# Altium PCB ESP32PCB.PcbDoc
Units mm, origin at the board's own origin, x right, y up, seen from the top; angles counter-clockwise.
Board outline 110 x 90 mm, 2 copper layers (Top Layer, Bottom Layer); 120 components, 72 nets, 375 pads, 60 vias.
Unrouted connection lines stored in the file: 1.
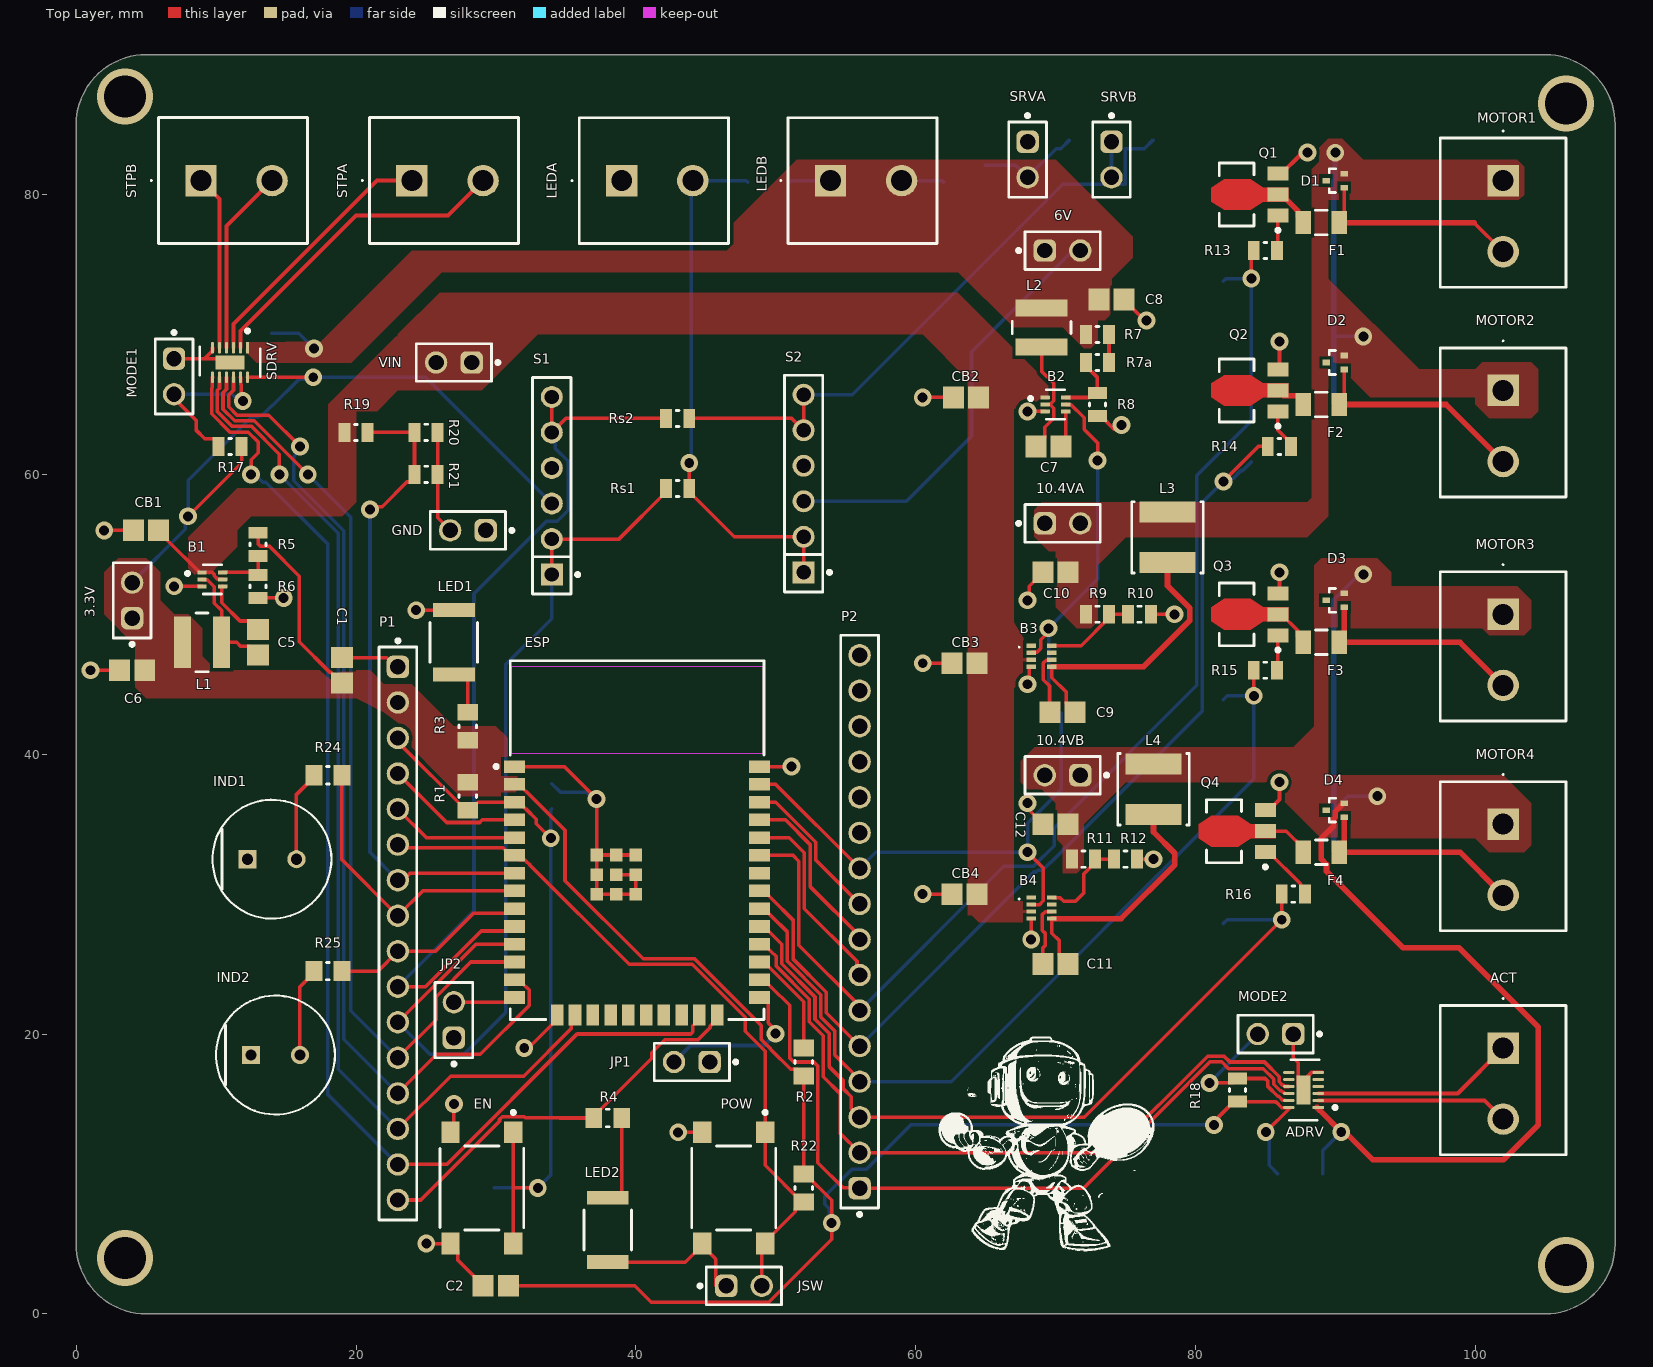
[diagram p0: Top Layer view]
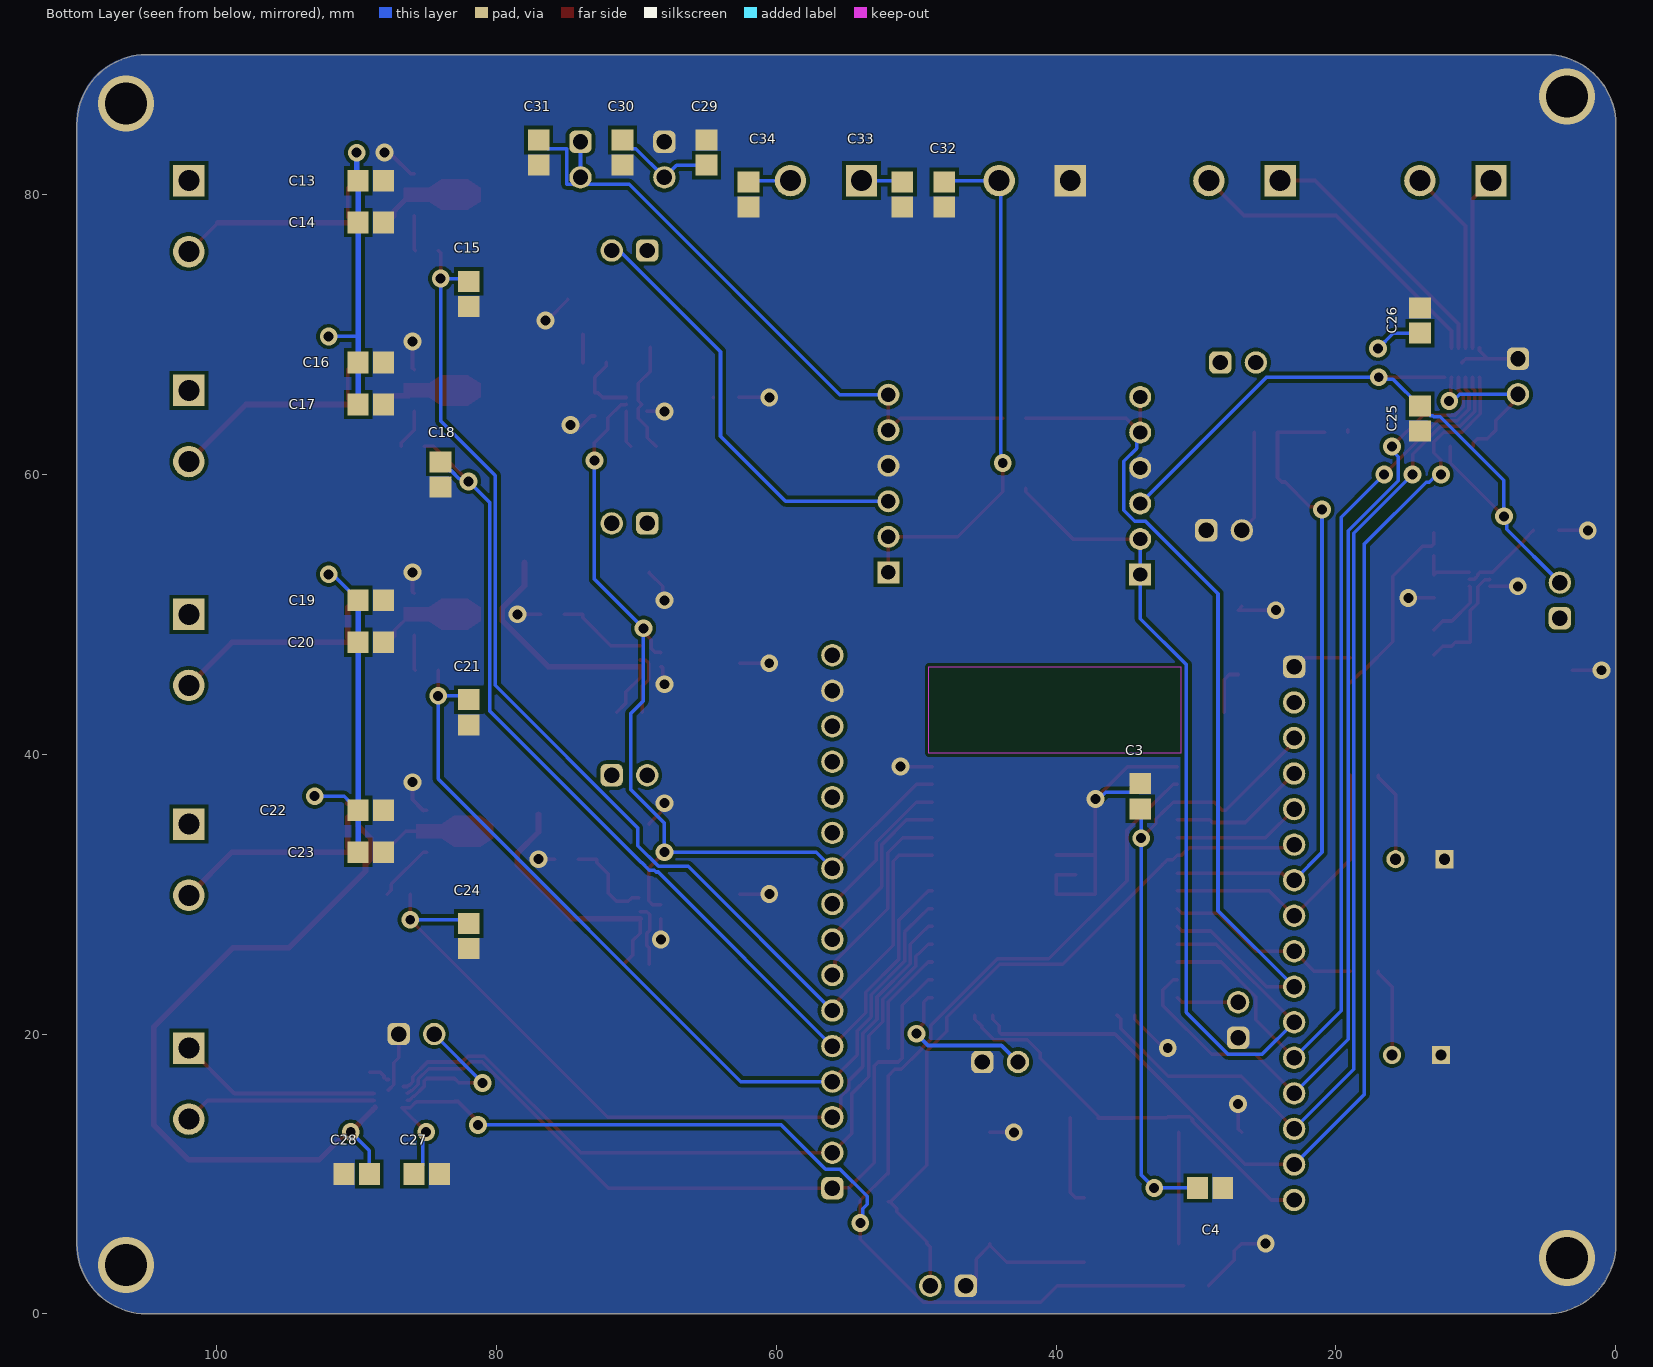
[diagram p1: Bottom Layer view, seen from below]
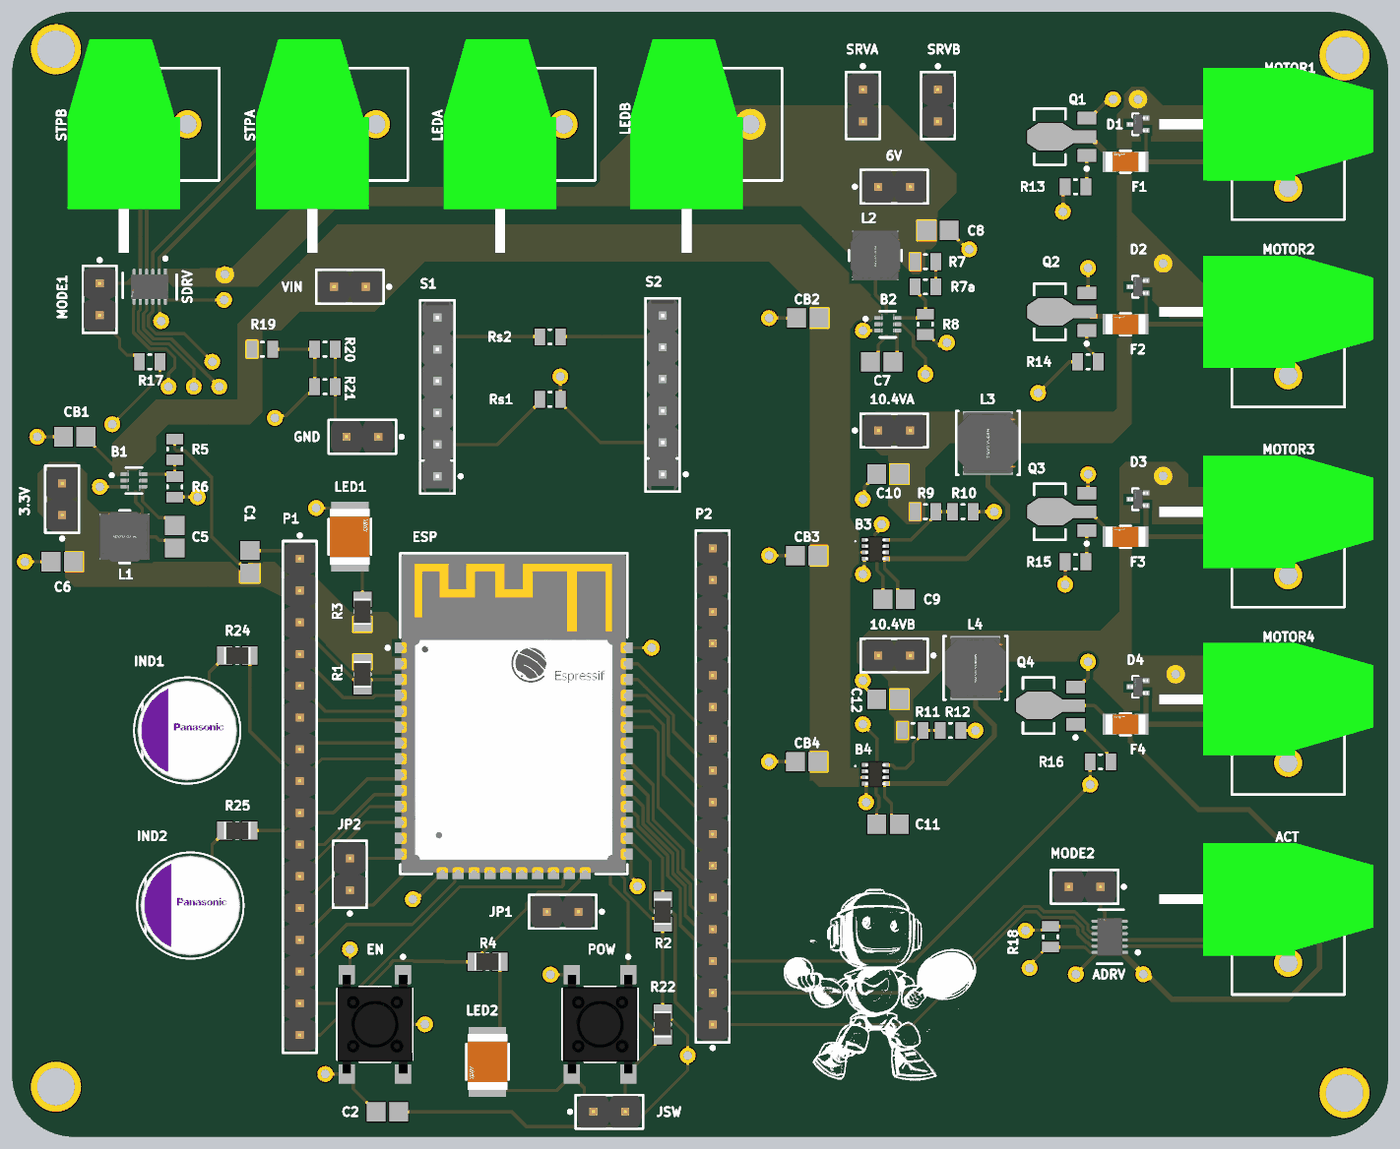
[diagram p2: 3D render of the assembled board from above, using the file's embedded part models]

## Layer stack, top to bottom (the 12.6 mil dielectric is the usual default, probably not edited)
Top Solder: solder mask 0.0102, Solder Resist, Dk 3.5
Top Layer: signal copper 0.0356
Dielectric 1: dielectric 0.32, FR-4, Dk 4.8
Bottom Layer: signal copper 0.0356
Bottom Solder: solder mask 0.0102, Solder Resist, Dk 3.5

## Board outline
0,5 ccw(c5,5) 5,0 105,0 ccw(c105,5) 110,5 110,85 ccw(c105,85) 105,90 5,90 ccw(c5,85) 0,85

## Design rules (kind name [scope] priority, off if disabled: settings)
Clearance Clearance_1 [IsPad] p1: gap=0.254 ignorepadtopadclearanceinfootprint=TRUE except(0.15: Arc-SMDPad Track-SMDPad SMDPad-SMDPad; 0.2: Arc-Arc Arc-Track Track-Track)
Clearance Clearance_1 [OnMid vs OnMid] p2: gap=0.254 ignorepadtopadclearanceinfootprint=FALSE except(0.15: Arc-Arc Arc-Track Arc-SMDPad Arc-Text Track-Track Track-SMDPad Track-Text SMDPad-SMDPad SMDPad-Text Text-Text) sourcerule=40 cellrowname=All cellrowtype=0 cellcolname=All cellcoltype=0 innerlayers=TRUE
Clearance Clearance_2 [(ExistsOnLayer('Top Layer') Or ExistsOnLayer('Bottom Layer')) vs (ExistsOnLayer('Top Layer') Or ExistsOnLayer('Bottom Layer'))] p3: gap=0.254 ignorepadtopadclearanceinfootprint=FALSE except(0.15: Arc-Arc Arc-Track Arc-SMDPad Arc-Text Track-Track Track-SMDPad Track-Text SMDPad-SMDPad SMDPad-Text Text-Text) sourcerule=40 cellrowname=All cellrowtype=0 cellcolname=All cellcoltype=0 outerlayers=TRUE
Clearance [All] p4: gap=0.254 ignorepadtopadclearanceinfootprint=FALSE ismatrix=TRUE
HoleSize [All] p1: absolutevalues=TRUE maxlimit=5 minlimit=0.025 maxpercent=80.000 minpercent=20.000
MinimumSolderMaskSliver [All] p1: minsoldermaskwidth=0.08
NetAntennae [All] p1 off: netantennaetolerance=0
PlaneClearance PlaneClearance_1 [(InNet('14.4V') OR InNet('10.4VA'))] p1: clearance=0
PlaneClearance [All] p2: clearance=0.508
PlaneConnect [All] p1: planeconnectstyle=Direct reliefexpansion=0.508 reliefentries=4 reliefconductorwidth=0.254 reliefairgap=0.254
PolygonConnect [All] p1: connectstyle=Direct reliefconductorwidth=0.254 reliefentries=4 polygonreliefangle="90 Angle" airgapwidth=0.254
RoutingVias [All] p1: holewidth=0.711 width=1.27 viastyle="Through Hole" minholewidth=0.711 minwidth=1.27 maxholewidth=0.711 maxwidth=1.27
SilkToSolderMaskClearance SilkToSolderMaskClearance_1 [(InNet('3.3V') AND InComponent('3.3V'))] p1: minsilkscreentomaskgap=0.254 clearancetoexposedcopper=TRUE
SilkToSolderMaskClearance [IsPad] p2: minsilkscreentomaskgap=0.16 clearancetoexposedcopper=TRUE
SolderMaskExpansion [All] p1: expansion=0.102 istentingtop=FALSE
SupplyNets "Schematic Supply Nets_1" [InNet('GND')] p1: voltage=0.000
Width [All] p1: maxlimit=0.5 minlimit=0.254 preferedwidth=0.254 minimp=50.000000 maximp=50.000000 favimp=50.000000
24 further rules are at their usual default settings.

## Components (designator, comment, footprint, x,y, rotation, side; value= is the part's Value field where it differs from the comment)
3.3V "3V3" 61300211121 3.994,50.997 r90 top
6V "6V" 61300211121 70.5,76 r0 top
10.4VA "10V4" 61300211121 70.5,56.5 r0 top
10.4VB "10V4" 61300211121 70.5,38.5 r180 top
ACT "EBAFA-02-D" EBAFA02D 101.994,18.997 r270 top
ADRV "DRV8835DSSR" FP-DSS0012A-IPC_A 87.724,15.997 r180 top
B1 "TPS562231DRLR" FP-DRL0006A-MFG 9.734,52.497 r0 top
B2 "TPS562231DRLR" FP-DRL0006A-MFG 69.994,64.997 r0 top
B3 "TPS563300DRLR" TPS62932DRLR 69,47 r0 top
B4 "TPS563300DRLR" TPS62932DRLR 69,29 r0 top
C1 "22uF" CAPC2013X145X50ML20T25 18.994,45.997 r270 top
C2 "0.1uF" CAPC2013X145X50ML20T25 29.994,1.997 r0 top
C3 "0.1uF" CAPC2013X145X50ML20T25 33.994,36.997 r270 bottom
C4 "0.1uF" CAPC2013X145X50ML20T25 28.994,8.997 r180 bottom
C5 "0.1uF" CAPC2013X145X50ML20T25 12.994,47.997 r90 top
C6 "47uF" CAPC2013X145X50ML20T25 4,46 r180 top
C7 "0.1uF" CAPC2013X145X50ML20T25 69.5,62 r0 top
C8 "47uF" CAPC2013X145X50ML20T25 74,72.5 r0 top
C9 "0.1uF" CAPC2013X145X50ML20T25 70.5,43 r180 top
C10 "47uF" CAPC2013X145X50ML20T25 70,53 r180 top
C11 "0.1uF" CAPC2013X145X50ML20T25 70,25 r180 top
C12 "47uF" CAPC2013X145X50ML20T25 70,35 r180 top
C13 "22uF" CAPC2013X145X50ML20T25 88.994,80.997 r180 bottom
C14 "0.1uF" CAPC2013X145X50ML20T25 88.994,77.997 r180 bottom
C15 "0.1uF" CAPC2013X145X50ML20T25 81.994,72.897 r270 bottom
C16 "22uF" CAPC2013X145X50ML20T25 88.994,67.997 r180 bottom
C17 "0.1uF" CAPC2013X145X50ML20T25 88.994,64.997 r180 bottom
C18 "0.1uF" CAPC2013X145X50ML20T25 84,60 r270 bottom
C19 "22uF" CAPC2013X145X50ML20T25 88.994,50.997 r180 bottom
C20 "0.1uF" CAPC2013X145X50ML20T25 88.994,47.997 r180 bottom
C21 "0.1uF" CAPC2013X145X50ML20T25 81.994,42.997 r270 bottom
C22 "22uF" CAPC2013X145X50ML20T25 88.994,35.997 r180 bottom
C23 "0.1uF" CAPC2013X145X50ML20T25 88.994,32.997 r180 bottom
C24 "0.1uF" CAPC2013X145X50ML20T25 81.994,26.997 r270 bottom
C25 "0.1uF" CAPC2013X145X50ML20T25 13.994,63.997 r270 bottom
C26 "0.1uF" CAPC2013X145X50ML20T25 13.994,70.997 r90 bottom
C27 "0.1uF" CAPC2013X145X50ML20T25 84.994,9.997 r180 bottom
C28 "0.1uF" CAPC2013X145X50ML20T25 89.994,9.997 r0 bottom
C29 "22uF" CAPC2013X145X50ML20T25 64.994,82.997 r90 bottom
C30 "0.1uF" CAPC2013X145X50ML20T25 70.994,82.997 r270 bottom
C31 "0.1uF" CAPC2013X145X50ML20T25 76.994,82.997 r270 bottom
C32 "0.1uF" CAPC2013X145X50ML20T25 47.994,79.997 r270 bottom
C33 "22uF" CAPC2013X145X50ML20T25 50.994,79.997 r270 bottom
C34 "0.1uF" CAPC2013X145X50ML20T25 61.994,79.997 r270 bottom
CB1 "10uF" CAPC2013X145X50ML20T25 4.994,55.997 r180 top
CB2 "10uF" CAPC2013X145X50ML20T25 63.6,65.5 r180 top
CB3 "10uF" CAPC2013X145X50ML20T25 63.5,46.5 r180 top
CB4 "10uF" CAPC2013X145X50ML20T25 63.5,30 r180 top
D1 "BAV99T-7-F" FP-SOT523-MFG 89.994,80.997 r180 top value=1.5pF
D2 "BAV99T-7-F" FP-SOT523-MFG 89.994,67.997 r180 top value=1.5pF
D3 "BAV99T-7-F" FP-SOT523-MFG 89.994,50.997 r180 top value=1.5pF
D4 "BAV99T-7-F" FP-SOT523-MFG 89.994,35.997 r180 top value=1.5pF
EN "EN" FP-PTS645SM43SMTR92LFS-MFG 28.994,8.997 r270 top
ESP "ESP32-WROOM-32E (4MB)" FP-ESP32-WROOM-32E_4MB-MFG 40.094,33.857 r0 top
F1 "" FP-GRM319-0_15-IPC_C 88.994,77.997 r180 top
F2 "" FP-GRM319-0_15-IPC_C 88.994,64.997 r180 top
F3 "" FP-GRM319-0_15-IPC_C 88.994,47.997 r180 top
F4 "" FP-GRM319-0_15-IPC_C 88.994,32.997 r180 top
GND "GND" 61300211121 27.994,55.997 r180 top
IND1 "" FP-OS-CON-TH-E12-d_0_6-MFG 13.994,32.497 r0 top
IND2 "" FP-OS-CON-TH-E12-d_0_6-MFG 14.244,18.497 r0 top
JP1 "BOOT" 61300211121 44,18 r180 top
JP2 "IO12" 61300211121 26.994,20.997 r90 top
JSW "" 61300211121 47.73,2 r0 top
L1 "3.3uH" FP-NR4012-MFG 8.994,47.997 r180 top
L2 "3.3uH" FP-NR4012-MFG 69,70.5 r90 top
L3 "6.8uH" FP-NRS5030-H_3_1-MFG 78,55.5 r90 top
L4 "6.8uH" FP-NRS5030-H_3_1-MFG 77,37.5 r90 top
LED1 "GREEN" FP-1812-L_4_5_0_3-W_3_2_0-MFG 26.994,47.997 r90 top
LED2 "YELLOW" FP-1812-L_4_5_0_3-W_3_2_0-MFG 37.994,5.997 r270 top
LEDA "EBAFA-02-D" EBAFA02D 38.994,80.997 r0 top
LEDB "EBAFA-02-D" EBAFA02D 53.914,80.997 r0 top
MODE1 "" 61300211121 6.994,66.997 r270 top
MODE2 "" 61300211121 85.724,19.997 r180 top
MOTOR1 "EBAFA-02-D" EBAFA02D 101.994,80.997 r270 top
MOTOR2 "EBAFA-02-D" EBAFA02D 101.994,65.997 r270 top
MOTOR3 "EBAFA-02-D" EBAFA02D 101.994,49.997 r270 top
MOTOR4 "EBAFA-02-D" EBAFA02D 101.994,34.997 r270 top
P1 "L_CONN" 61301611121 22.994,27.187 r270 top
P2 "R_CONN" 61301611121 55.994,28.027 r90 top
POW "" FP-PTS645SM43SMTR92LFS-MFG 46.994,8.997 r270 top
Q1 "2SC5566-TD-E" ONSC-SOT-89_PCP-1-3-419AU_V 82.994,79.997 r90 top
Q2 "2SC5566-TD-E" ONSC-SOT-89_PCP-1-3-419AU_V 82.994,65.997 r90 top
Q3 "2SC5566-TD-E" ONSC-SOT-89_PCP-1-3-419AU_V 82.994,49.997 r90 top
Q4 "2SC5566-TD-E" ONSC-SOT-89_PCP-1-3-419AU_V 82.094,34.497 r90 top
R1 "10k" RESC2013X60X35ML10T20 27.994,36.997 r270 top
R2 "10k" RESC2013X60X35ML10T20 52,18 r90 top
R3 "100" RESC2013X60X35ML10T20 27.994,41.997 r90 top
R4 "100" RESC2013X60X35ML10T20 37.994,13.997 r0 top
R5 "45.3k" RESC2013X50X30LL20T20 13,55 r270 top
R6 "10k" RESC2013X50X30LL20T20 12.994,51.997 r270 top
R7 "45.3k" RESC2013X50X30LL20T20 73,70 r0 top
R7a "45.3k" RESC2013X50X30LL20T20 72.994,67.997 r0 top
R8 "10k" RESC2013X50X30LL20T20 72.994,64.997 r270 top
R9 "120k" RESC2013X50X30LL20T20 73,50 r0 top
R10 "10k" RESC2013X50X30LL20T20 76,50 r0 top
R11 "120k" RESC2013X50X30LL20T20 72,32.5 r0 top
R12 "10k" RESC2013X50X30LL20T20 75,32.5 r0 top
R13 "1k" RESC2013X50X30LL20T20 84.994,75.997 r0 top
R14 "1k" RESC2013X50X30LL20T20 85.994,61.997 r0 top
R15 "1k" RESC2013X50X30LL20T20 84.994,45.997 r0 top
R16 "1k" RESC2013X50X30LL20T20 86.994,29.997 r0 top
R17 "10k" RESC2013X50X30LL20T20 11,62 r0 top
R18 "10k" RESC2013X50X30LL20T20 83,16 r270 top
R19 "10k" RESC2013X50X30LL20T20 19.994,62.997 r0 top
R20 "100k" RESC2013X50X30LL20T20 25.006,63.003 r0 top
R21 "100k" RESC2013X50X30LL20T20 25.006,60.003 r0 top
R22 "10k" RESC2013X60X35ML10T20 51.994,8.997 r270 top
R24 "100" RESC2013X60X35ML10T20 17.994,38.497 r180 top
R25 "100" RESC2013X60X35ML10T20 17.994,24.497 r180 top
Rs1 "0" RESC2013X50X30LL20T20 42.994,58.997 r0 top
Rs2 "0" RESC2013X50X30LL20T20 42.994,63.997 r0 top
S1 "" FP-22-28-4060-MFG 33.994,59.187 r90 top
S2 "" FP-22-28-4060-MFG 51.994,59.347 r90 top
SDRV "DRV8835DSSR" FP-DSS0012A-IPC_A 10.994,67.997 r270 top
SRVA "" 61300211121 68,82.5 r270 top
SRVB "" 61300211121 74,82.5 r270 top
STPA "EBAFA-02-D" EBAFA02D 24,81 r0 top
STPB "EBAFA-02-D" EBAFA02D 8.92,81 r0 top
VIN "14.4V" 61300211121 26.994,67.997 r180 top

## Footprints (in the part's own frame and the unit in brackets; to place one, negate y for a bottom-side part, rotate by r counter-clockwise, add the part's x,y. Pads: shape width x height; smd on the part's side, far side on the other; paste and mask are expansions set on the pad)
61300211121 [mm] "Pin Header, pitch 2.54 mm, THT, Vertical, single row, 2p"
  rrect50% 1.6x1.6 hole 1.1: 1(-1.27,0)
  round 1.6 hole 1.1: 2(1.27,0)
  silkscreen extent -3.26,-1.35 2.69,1.35, body extent -2.54,-1.27 2.54,1.27, height 8.57
61301611121 [mm] "Pin Header, pitch 2.54 mm, THT, Vertical, single row, 16p"
  rrect50% 1.6x1.6 hole 1.1: 1(-19.05,0)
  round 1.6 hole 1.1: 2(-16.51,0) 3(-13.97,0) 4(-11.43,0) 5(-8.89,0) 6(-6.35,0) 7(-3.81,0) 8(-1.27,0) 9(1.27,0) 10(3.81,0) 11(6.35,0) 12(8.89,0) 13(11.43,0) 14(13.97,0) 15(16.51,0) 16(19.05,0)
  silkscreen extent -21.04,-1.35 20.47,1.35, body extent -20.32,-1.27 20.32,1.27, height 8.57
CAPC2013X145X50ML20T25 [mm] "Chip Capacitor, 2-Leads, Body 2.00x1.25mm, IPC Low Density"
  rect 1.5x1.55 smd: 1(-0.9,0) 2(0.9,0)
  body extent -1.1,-0.72 1.1,0.72, height 1.45
EBAFA02D [mm]
  rect 2.25x2.25 hole 1.5: 1(0,0)
  round 2.25 hole 1.5: 2(5.08,0)
  silkscreen extent -3.6,-4.5 7.62,4.5, body extent -4.5,-10.3 4.5,6.8, height 5.08
FP-22-28-4060-MFG [mm]
  rect 1.57x1.57 hole 1.02 paste-2539.97 mask+0: 1(-6.35,0)
  round 1.57 hole 1.02 paste-2539.97 mask+0: 2(-3.81,0) 3(-1.27,0) 4(1.27,0) 5(3.81,0) 6(6.35,0)
  silkscreen extent -7.75,-1.97 7.75,1.37, body extent -7.85,-1.47 7.85,1.47, height 0.25
FP-1812-L_4_5_0_3-W_3_2_0-MFG [mm]
  rect 1x3 smd paste+0 mask+0: 1(-2.3,0) 2(2.3,0)
  silkscreen extent -1.43,-1.7 1.43,1.7, body extent -2.9,-1.8 2.9,1.8, height 0.25
FP-DRL0006A-MFG [mm]
  rrect33% 0.67x0.3 smd paste+0 mask+0: 1(-0.74,0.5) 2(-0.74,0) 3(-0.74,-0.5) 4(0.74,-0.5) 5(0.74,0) 6(0.74,0.5)
  silkscreen extent -1.9,-1.05 0.65,1.05, body extent -1.17,-1.1 1.17,1.1, height 0.25
FP-DSS0012A-IPC_A [mm]
  rect 0.806x0.242 smd paste+0 mask+0: 1(-1.053,1.25)
  rrect100% 0.806x0.242 smd paste+0 mask+0: 2(-1.053,0.75) 3(-1.053,0.25) 4(-1.053,-0.25) 5(-1.053,-0.75) 6(-1.053,-1.25) 7(1.053,-1.25) 8(1.053,-0.75) 9(1.053,-0.25) 10(1.053,0.25) 11(1.053,0.75) 12(1.053,1.25)
  rect 1x2.1 smd paste-1000 mask+0: 13(0,0)
  silkscreen extent -2.38,-2.16 1.02,2.16, body extent -1.96,-2 1.96,2, height 0.25
FP-ESP32-WROOM-32E_4MB-MFG [mm]
  rect 1.5x0.9 smd paste+0 mask+0: 1(-8.75,5.26) 2(-8.75,3.99) 3(-8.75,2.72) 4(-8.75,1.45) 5(-8.75,0.18) 6(-8.75,-1.09) 7(-8.75,-2.36) 8(-8.75,-3.63) 9(-8.75,-4.9) 10(-8.75,-6.17) 11(-8.75,-7.44) 12(-8.75,-8.71) 13(-8.75,-9.98) 14(-8.75,-11.25) 25(8.75,-11.25) 26(8.75,-9.98) 27(8.75,-8.71) 28(8.75,-7.44) 29(8.75,-6.17) 30(8.75,-4.9) 31(8.75,-3.63) 32(8.75,-2.36) 33(8.75,-1.09) 34(8.75,0.18) 35(8.75,1.45) 36(8.75,2.72) 37(8.75,3.99) 38(8.75,5.26)
  rect 0.9x1.5 smd paste+0 mask+0: 15(-5.71,-12.5) 16(-4.44,-12.5) 17(-3.17,-12.5) 18(-1.9,-12.5) 19(-0.63,-12.5) 20(0.64,-12.5) 21(1.91,-12.5) 22(3.18,-12.5) 23(4.45,-12.5) 24(5.72,-12.5)
  rect 0.9x0.9 smd paste+0 mask+0: 39(-2.9,-3.86) 39(-2.9,-2.46) 39(-2.9,-1.06) 39(-1.5,-3.86) 39(-1.5,-2.46) 39(-1.5,-1.06) 39(-0.1,-3.86) 39(-0.1,-2.46) 39(-0.1,-1.06)
  Keep-Out Layer region: -9,6.205 9,6.205 9,12.395 -9,12.395
  Keep-Out Layer region: -9,6.205 9,6.205 9,12.395 -9,12.395
  silkscreen extent -10.2,-12.83 9.08,12.83, body extent -9.6,-13.35 9.6,12.93, height 0.25
FP-GRM319-0_15-IPC_C [mm]
  rect 1.106x1.658 smd paste+0 mask+0: 1(-1.276,0) 2(1.276,0)
  silkscreen extent -0.42,-0.87 0.42,0.87, body extent -1.93,-0.97 1.93,0.97, height 0.25
FP-NR4012-MFG [mm]
  rect 1.2x3.7 smd paste+0 mask+0: 1(-1.4,0) 2(1.4,0)
  silkscreen extent -0.43,-2.1 0.43,2.1, body extent -2.2,-2.2 2.2,2.2, height 0.25
FP-NRS5030-H_3_1-MFG [mm]
  rect 1.5x4 smd paste+0 mask+0: 1(-1.8,0) 2(1.8,0)
  silkscreen extent -2.55,-2.55 2.55,2.55, body extent -2.65,-2.65 2.65,2.65, height 0.25
FP-OS-CON-TH-E12-d_0_6-MFG [mm]
  rect 1.3x1.3 hole 0.8 paste-2539.97 mask+0: 1(-1.75,0)
  round 1.3 hole 0.8 paste-2539.97 mask+0: 2(1.75,0)
  silkscreen extent -4.25,-4.25 4.25,4.25, body extent -4.35,-4.35 4.35,4.35, height 0.25
FP-PTS645SM43SMTR92LFS-MFG [mm]
  rect 1.55x1.3 smd paste+0 mask+0: 1(-3.975,2.25) 2(3.975,2.25) 3(-3.975,-2.25) 4(3.975,-2.25)
  silkscreen extent -5.52,-3 3,3, body extent -4.85,-3.1 4.85,3.1, height 0.25
FP-SOT523-MFG [mm]
  rect 0.51x0.4 smd paste+0 mask+0: 1(-0.645,0.5) 2(-0.645,-0.5) 3(0.645,0)
  silkscreen extent -0.02,-0.85 0.43,0.85, body extent -1,-0.95 1,0.95, height 0.25
ONSC-SOT-89_PCP-1-3-419AU_V [mm] "SOT89, 3-Leads, Body 4.5x2.5mm, Pitch 1.5mm"
  rect 1x1.5 smd: 1(-1.5,-2.9) 2(0,-2.9) 3(1.5,-2.9)
  Top Layer region: -0.5,-3.65 -0.5,-1.85 -1.1,-0.95 -1.1,0.95 -0.5,1.85 0.5,1.85 1.1,0.95 1.1,-0.95 0.5,-1.85 0.5,-3.65
  silkscreen extent -2.67,-3.03 2.25,1.3, body extent -2.25,-1.2 2.25,1.3, height 1.6
RESC2013X50X30LL20T20 [mm] "Chip Resistor, 2-Leads, Body 2.00x1.25mm, IPC High Density"
  rect 0.85x1.35 smd: 1(-0.825,0) 2(0.825,0)
  silkscreen extent -0.1,-0.58 0.1,0.58, body extent -1.1,-0.72 1.1,0.72, height 0.5
RESC2013X60X35ML10T20 [mm] "Chip Resistor, 2-Leads, Body 2.1x1.35mm, IPC Low Density"
  rect 1.2x1.45 smd: 1(-1,0) 2(1,0)
  silkscreen extent -0.1,-0.63 0.1,0.63, body extent -1.05,-0.68 1.05,0.67, height 0.6
TPS62932DRLR [mm]
  rect 0.67x0.3 smd: 1(-0.74,0.75) 2(-0.74,0.25) 3(-0.74,-0.25) 4(-0.74,-0.75) 5(0.74,-0.75) 6(0.74,-0.25) 7(0.74,0.25) 8(0.74,0.75)
  silkscreen extent -1.65,0.6 -1.55,0.7, body extent -0.8,-1.05 0.8,1.05, height 0.6

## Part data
3.3V 6V 10.4VA 10.4VB GND JP1 JP2 JSW MODE1 MODE2 SRVA SRVB VIN: library part CMP-1712-00002-6, Color=Black, Contact Resistance=20mΩ, Current Rating=3A, Max Operating Temperature=125°C, Min Operating Temperature=-40°C, Operating Supply Voltage=250V
ACT LEDA LEDB MOTOR1 MOTOR2 MOTOR3 MOTOR4 STPA STPB: "Connector", Manufacturer_Name="Adam Tech"
ADRV SDRV: library part CMP-00024-00007-1, "Brush DC Motor Controller, 1.5A, PDSO12", Case/Package=HVSON, Max Operating Temperature=85°C, Min Operating Temperature=-40°C, Nominal Supply Voltage=3V
B1 B2: library part CMP-04918-000372-1, "POWER MANAGEMENT"
B3 B4: "Integrated Circuit", Manufacturer_Name="Texas Instruments", Mouser Part Number=595-TPS563300DRLR
C1 C2 C3 C4 C5 C6 C7 C8 C9 C10 C11 C12 C13 C14 C15 C16 C17 C18 C19 C20 C21 C22 C23 C24 C25 C26 C27 C28 C29 C30 C31 C32 C33 C34 CB1 CB2 CB3 CB4: library part CMP-1036-04819-2, Manufacturer=Kemet, Part Number=C0805C225K9PACTU
D1 D2 D3 D4: library part CMP-12791-000024-1, "DIODE ARRAY GP 85V 75MA SOT523", Capacitance=1.5pF, Forward Current=75mA, Manufacturer="Diodes Inc.", Max Junction Temp=+150°C, Max Repetitive Reverse Voltage=85V, Max Surge Forward Current=0.5A, Package=SOT523, Peak Reverse Current=2uA, Temperature="-65°C to +150°C", Temperature Range Low=-65°C
EN POW: library part CMP-2000-05160-2, "SWITCH TACTILE SPST-NO 0.05A 12V", Case/Package=SMD/SMT, Color=Black, Contact Resistance=100mR, Current Rating=50mA, Max Operating Temperature=60°C, Max Voltage Rating (DC)=12V, Min Operating Temperature=-20°C, Operating Force=160gf, Package Quantity=1
ESP: library part CMP-194065-000026-1, "RX TXRX MOD WIFI TRACE ANT SMD"
F1 F2 F3 F4: library part CMP-1037-03764-2, "Chip Multilayer Ceramic Capacitors for General Purpose, 1206, 22000pF, C0G, 30ppm/°C, 5%, 50V", Capacitance=22nF, Case Code (Imperial)=1206, Case Code (Metric)=3216, Dielectric=C0G, Dielectric Material=Ceramic, Insulation Resistance=10GR, Max Operating Temperature=125°C, Min Operating Temperature=-55°C, Package Quantity=4000, Temperature Coefficient=30ppm/°C, Tolerance=5%, Voltage=50V
IND1 IND2: library part CMP-05428-001155-1, "Conductive Polymer Aluminum Solid Capacitors (OS-CON) 270uF ±20% 16V RADIAL TH 8x12mm", Capacitance=270uF, Case/Package=Radial, ESR (Equivalent Series Resistance)=11mR, Leakage Current=864uA, Max Operating Temperature=105°C, Min Operating Temperature=-55°C, Package Quantity=1000, Ripple Current=5A, Tolerance=20%, Voltage=16V
L1 L2: library part CMP-14484-001001-1, "SMD Power Inductors 3.3uH ±20% 1.4A 84mΩ", Case/Package=4012, Current Rating=1.7A, DC Resistance (DCR)=84mR, Inductance Tolerance=20%, Max Operating Temperature=125°C, Min Operating Temperature=-25°C, Package Quantity=1, Resistor Type=Wirewound, Saturation Current=1.4A, Self Resonant Frequency=60MHz, Test Frequency=100kHz
L3 L4: library part CMP-14484-000674-1, "Inductor Power Shielded Wirewound 6.8uH 20% 100KHz Ferrite 2.3A 67.6mΩ DCR T/R", Case/Package=5030, Current Rating=2.3A, DC Resistance (DCR)=52mR, Max DC Current=2.5A, Max Operating Temperature=120°C, Min Operating Temperature=-25°C, Package Quantity=500, Self Resonant Frequency=22MHz, Test Frequency=100kHz, Tolerance=20%
LED1 LED2: library part CMP-1040-01548-3, "General Purpose Ceramic Capacitor, 1812, 470nF, 10%, X7R, 15%, 100V", Capacitance=470nF, Case Code (Imperial)=1812, Case Code (Metric)=4532, Dielectric=X7R, Max Operating Temperature=125°C, Min Operating Temperature=-55°C, Package Quantity=1, Tolerance=10%, Voltage=100V
P1 P2: library part CMP-1502-01095-4, Color=Black, Contact Resistance=20mΩ, Current Rating=3A, Max Operating Temperature=105°C, Min Operating Temperature=-40°C, Operating Supply Voltage=250V
Q1 Q2 Q3 Q4: library part CMP-1048-00945-1, "Bipolar Transistor, 50 V, 4 A, Low VCE(sat), NPN Single, 3-Pin SOT-89, Pb-Free, Tape and Reel", Manufacturer="On Semiconductor"
R1 R2 R3 R4 R22 R24 R25: library part CMP-2100-03671-1, "Chip Resistor, 1 KOhm, +/- 1%, 125 mW, -55 to 155 degC, 0805 (2012 Metric), RoHS, Tape and Reel", Case Code (Imperial)=0805, Case Code (Metric)=2012, Manufacturer=Yageo, Max Operating Temperature=155degC, Max Power Dissipation=125mW, Min Operating Temperature=-55degC, Package Description="2-Pin Surface Mounted Device, Body 2 x 1.25 mm", Package Quantity=1, Resistance=1KOhm, Temperature Coefficient=100ppm/degreesC, Tolerance=1%, Voltage Rating=150V
R5 R6 R7 R7a R8 R9 R10 R11 R12 R13 R14 R15 R16 R17 R18 R19 R20 R21 Rs1 Rs2: library part CMP-2001-04896-1, Manufacturer="Vishay Dale", Part Number=CRCW08050000Z0EA
S1 S2: library part CMP-04776-000763-1, "CONN HEADER VERT 6POS 2.54MM", Color=Black, Contact Resistance=20mR, Current Rating=4A, Max Operating Temperature=75°C, Max Voltage Rating (AC)=250V, Max Voltage Rating (DC)=250.25kV, Min Operating Temperature=0°C, Package Quantity=1

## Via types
v1: diameter 1.27, hole 0.711, Top Layer to Bottom Layer, 56 vias
v2: diameter 4, hole 3, Top Layer to Bottom Layer, 4 vias

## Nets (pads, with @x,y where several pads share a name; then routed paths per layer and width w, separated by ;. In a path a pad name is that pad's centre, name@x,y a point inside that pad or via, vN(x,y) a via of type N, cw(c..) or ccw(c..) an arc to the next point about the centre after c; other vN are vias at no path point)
3.3V: 3.3V.1 3.3V.2 ADRV.12 C1.2 C2.2 C6.1 C25.1 C27.1 ESP.2 L1.2 P1.2 R1.1 R2.1 R3.1 R5.1 R17.2 R18.2 R22.1 S1.3 SDRV.12 | length 181.1
  Top Layer w0.254: v1(8,57) 11.825,60.825 R17.2 ; SDRV.12 v1(16.944,66.944) ; R5.1 13,55.026 13.149,54.877 13.79,54.877 15.947,52.72 15.947,48.027 18.104,45.87 18.196,45.87 18.969,45.097 C1.2 ; C2.2 39.914,1.997 41.092,0.819 49.489,0.819 54,5.33 54,8.116 52.119,9.997 R22.1 51.994,16.994 R2.1 51.527,17.473 51.072,17.473 49.648,18.898 49.648,18.924 48.966,19.605 48.966,20.605 44.192,25.379 40.52,25.379 34.937,30.962 34.937,34.576 32.191,37.322 32.169,37.322 31.644,37.847 ESP.2 ; v1(81.325,13.5) 81.325,13.75 82.75,15.175 R18.2 83.003,15.172 85.686,15.172 85.722,15.137 85.781,15.137 86.177,14.741 86.768,14.741 v1(85.026,13)
  Bottom Layer w0.254: 3.3V.2 7.806,56.08 7.806,56.806 v1(8,57) 8,59.57 12.554,64.124 13.019,64.124 13.079,64.184 13.256,64.184 13.969,64.897 14.019,64.897 15.928,66.807 16.807,66.807 v1(16.944,66.944) 24.967,66.944 S1.3 ; v1(54,6.5) 53.827,6.673 53.827,7.516 53.511,7.832 53.511,8.399 55.448,10.336 56.483,10.336 59.646,13.5 v1(81.325,13.5) ; v1(85.026,13) 85.026,12.725 85.271,12.481 85.271,10.62 C27.1
6V: 6V.1 6V.2 C8.1 C26.1 C29.1 C30.1 C33.1 C34.1 L2.2 LEDB.1 LEDB.2 R7.1 S2.3 SDRV.1 SRVA.2 | length 47.5
  Top Layer w0.254: S2.3 S2.3@52.245,57.826
  Bottom Layer w0.254: C26.1 15.903,70.097 v1(17,69) ; C33.1 51.094,80.997 LEDB.1 ; S2.3 52,58.071 52.006,58.077 59.344,58.077 63.994,62.727 63.994,68.764 6V.2@71.23,76 ; LEDB.2 61.894,80.997 C34.1 ; C29.1 67.133,82.097 SRVA.2 70.044,83.274 70.371,83.274 C30.1
10.4VA: 10.4VA.1 10.4VA.2 C10.1 C13.1 C14.1 C16.1 C17.1 D1.2 D2.2 L3.2 MOTOR1.1 MOTOR2.1 R9.1 | length 20.2
  Bottom Layer w0.254: 89.894,70 90.035,69.859 v1(92,69.859)
  Bottom Layer w0.4: C17.1 C16.1 89.894,70 C14.1 C13.1 89.994,81.097 v1(89.994,82.997)
10.4VB: 10.4VB.1 10.4VB.2 ADRV.1 C12.1 C19.1 C20.1 C22.1 C23.1 C28.1 D3.2 D4.2 L4.2 MOTOR3.1 MOTOR4.1 R11.1 | length 78.9
  Top Layer w0.4: ADRV.1@88.677,14.747 88.701,14.747 88.858,14.59 88.858,14.566 v1@90.421,13.003 ; v1(90.421,13) 90.681,13 92.681,11 102,11 104.5,13.5 104.5,20.5 98.833,26.167 94.833,26.167 89.367,31.633 89.367,32.127 89,32.494 89,34 89.881,34.881 89.881,35.381 90,35.5 90,35.914 90.584,36.497 D4.2
  Bottom Layer w0.254: C28.1 89.094,11.673 v1(90.421,13) ; C22.1 89.894,36.022 90.517,36.645 90.542,36.645 90.896,37 v1(93,37) ; C19.1 89.894,51.022 91.73,52.859 v1(92,52.859)
  Bottom Layer w0.4: C23.1 C22.1 ; C22.1@89.894,36.022 C20.1 C19.1
14.4V: B1.1 B1.5 B2.1 B3.3 B4.3 CB1.1 CB2.1 CB3.1 CB4.1 R19.1 VIN.1 VIN.2 | length 6.4
  Top Layer w0.254: CB1.1@5.894,55.972 CB1.1 6.517,55.374 6.517,55.289 8.809,52.997 B1.1 9.71,52.997 9.862,52.845 9.862,52.762 10.103,52.52 10.451,52.52 B1.5 ; R19.1 R19.1@19.169,63.202 ; CB2.1@64.5,65.475 CB2.1
BOOT: ESP.25 JP1.2 | length 11.3
  Top Layer w0.254: ESP.25 49.144,22.607 49.467,22.284 49.467,20.79 49.982,20.275 v1(49.982,20.026)
  Bottom Layer w0.254: JP1.2 43.911,19.181 49.163,19.181 49.982,20 v1(49.982,20.026)
EN: C3.2 C4.1 EN.1 EN.2 ESP.3 P1.3 R1.2 | length 55.1
  Top Layer w0.254: P1.3 22.994,40.872 27.869,35.997 R1.2 28.119,35.997 28.699,36.577 ESP.3 31.644,36.577 32.169,36.052 32.191,36.052 32.89,35.353 32.89,35.031 v1(33.921,34) ; EN.2 31.244,8.997 ; EN.1 31.244,8.997 ; v1@33,9 v1(32.997,8.997) 31.244,8.997
  Bottom Layer w0.254: C4.1 v1(32.997,8.997) 33.921,9.921 v1(33.921,34) 33.921,36.025 C3.2
GND: ADRV.6 ADRV.13 B1.3 B2.3 B3.4 B4.4 C1.1 C2.1 C3.1 C4.2 C6.2 C8.2 C10.2 C12.2 C13.2 C14.2 C15.2 C16.2 C17.2 C18.2 C19.2 C20.2 C21.2 C22.2 C23.2 C24.2 C25.2 C26.2 C27.2 C28.2 C29.2 C30.2 C31.2 C32.2 C33.2 C34.2 CB1.2 CB2.2 CB3.2 CB4.2 EN.3 EN.4 ESP.1 ESP.15 ESP.38 ESP.39 GND.1 GND.2 IND1.1 IND2.1 JP1.1 JP2.1 JSW.1 LED1.2 LED2.2 LEDA.1 MODE1.1 MODE2.1 P1.1 P2.15 POW.3 POW.4 Q1.3 Q2.3 Q3.3 Q4.3 R6.2 R8.2 R10.2 R12.2 R20.2 R21.2 S1.4 S2.4 SDRV.6 SDRV.13 SRVA.1 | length 116.9
  Top Layer w0.254: v1(1.016,46) C6.2 ; v1(2.003,55.997) CB1.2 ; MODE1.1 6.995,68.266 9.174,68.266 ; v1(7.003,51.997) B1.3 ; SDRV.6 9.744,68.836 9.174,68.266 ; SDRV.13 10.725,68.266 9.174,68.266 ; R6.2 v1(14.828,51.172) ; C1.1 22.186,46.897 22.846,46.237 P1.1 ; v1(24.297,50.297) LED1.2 LED1.2@26.724,50.567 ; v1(25.022,5.022) EN.4 27.267,4.499 27.267,3.849 29.094,2.022 C2.1 ; R20.2 R21.2 25.831,56.89 GND.2 ; EN.3 27,13.229 v1(27,15) ; ESP.1 34.883,39.117 v1(37.194,36.806) ESP.39@37.194,32.797 ; v1(32.026,19) 32.22,19.194 32.52,19.194 34.384,21.057 ESP.15 ; LED2.2 43.544,3.697 POW.4@44.744,4.897 ; ESP.39@38.594,31.397 39.994,31.397 39.994,29.997 38.594,29.997 37.194,29.997 37.194,31.397 ESP.39@37.194,32.797 ; ESP.39@39.994,32.797 38.594,32.797 ESP.39@37.194,32.797 ; v1(43.028,12.972) POW.3 ; POW.4 POW.4@44.744,4.897 ; JSW.1@45.724,1.997 45.724,3.917 POW.4@44.744,4.897 ; ESP.38 v1(51.117,39.117) ; v1(60.5,30) CB4.2 ; v1(60.5,65.5) CB2.2 ; v1(60.509,46.5) CB3.2 ; v1(68,36.5) 68.194,36.306 68.194,35.931 69.1,35.025 C12.2 ; v1(68,45) 68.13,45.13 68.13,46.227 68.153,46.25 B3.4 ; v1(68,51) 68.118,51.118 68.118,51.993 69.1,52.975 C10.2 ; v1(68,64.5) v1(68,64.5) 69.252,64.499 B2.3 ; v1(68.26,26.76) B4.4 ; R8.2 73.244,64.172 74.179,63.237 74.465,63.524 v1(74.72,63.524) ; C8.2 74.9,72.475 76.375,71 v1(76.5,71) ; R12.2 v1(77,32.5) ; R10.2 v1(78.5,50) ; Q4.3 Q4.3@85.244,35.997 ; Q3.3 Q3.3@86.01,51.613 ; Q2.3 Q2.3@86,67.604 ; Q1.3 Q1.3@86.144,81.497 ; MODE2.1 86.994,18.311 87.351,17.954 87.351,16.37 ADRV.13 ; v1@87.452,82.806 87.806,82.806 v1(88,83) ; ADRV.13@87.724,16.747 87.877,16.747 88,16.87 88.043,16.87 88.043,17.001 88.295,17.253 ADRV.6@89.052,17.253
  Top Layer w0.3: Q4.3@85.244,35.997 86,36.754 v1(86,38) ; Q2.3@86,67.604 v1(86,69.5) ; Q3.3@86.01,51.613 v1(86.01,53) ; Q1.3@86.144,81.497 v1@87.452,82.806
  Bottom Layer w0.254: C3.1 34.617,37.274 36.451,37.274 36.919,36.806 v1(37.194,36.806) ; v1@74.72,63.249 v1(74.72,63.524)
  other v2: 106.5,3.5 3.5,4 106.5,86.5 3.5,87
IO2: ESP.24 P1.16 R4.1 | length 29
  Top Layer w0.254: P1.16 24.637,8.137 30.257,13.757 30.257,13.887 30.454,14.084 32.033,14.084 32.093,14.024 34.542,14.024 34.569,13.997 R4.1 36.994,14.122 41.145,18.274 41.145,18.657 42.073,19.585 44.448,19.585 45.331,20.468 45.331,20.574 45.814,21.057 ESP.24
IO4: ADRV.10 ESP.26 P2.1 | length 54.9
  Top Layer w0.254: ESP.26 49.144,23.877 49.669,23.352 49.691,23.352 50.998,22.045 50.998,18.285 51.283,18 52.717,18 53.002,17.715 53.002,10.811 54.813,9 55.971,9 P2.1 71.997,8.977 81.035,18.016 81.877,18.016 82.366,17.527 84.84,17.527 85.586,16.781 85.586,16.415 86.056,15.945 86.128,15.945 86.23,15.843 86.304,15.843 ADRV.10@86.394,15.753
IO5: C24.1 ESP.29 P2.3 R16.1 | length 58.9
  Top Layer w0.254: ESP.29 49.144,27.687 49.669,27.162 49.691,27.162 50.431,26.421 50.431,25.024 52.808,22.647 52.808,21.051 53.81,20.049 53.81,17.682 54.813,16.68 54.813,16.108 55.404,15.517 55.404,14.647 P2.3 72.057,14.057 v1(86.169,28.169) R16.1
  Bottom Layer w0.254: C24.1 82.265,28.169 v1(86.169,28.169)
IO12: ESP.14 JP2.2 | length 4.5
  Top Layer w0.254: JP2.2 27.011,22.284 31.021,22.284 ESP.14
IO13: ESP.16 P1.14 SDRV.8 | length 76.4
  Top Layer w0.254: SDRV.8 10.242,66.943 10.242,66.16 10.087,66.005 10.087,64.494 11.156,63.425 12.548,63.425 14.524,61.449 v1(14.524,60) ; P1.14 26.769,16.993 31.993,16.993 35.39,20.39 35.39,21.094 ESP.16
  Bottom Layer w0.254: v1(14.524,60) 18.727,55.797 18.727,17.484 P1.14
IO14: ESP.13 P1.13 SDRV.10 | length 72.5
  Top Layer w0.254: SDRV.10 11.244,66.019 10.895,65.671 10.895,64.829 11.491,64.233 13.767,64.233 v1(16,62) ; P1.13 25.783,18.546 28.874,18.546 32.371,22.043 32.371,23.172 32.191,23.352 32.169,23.352 31.644,23.877 ESP.13
  Bottom Layer w0.254: v1(16,62) 16,61.725 15.54,61.265 15.54,59.555 19.131,55.964 19.131,19.62 P1.13
IO15: ESP.23 P1.15 SDRV.7 | length 89.7
  Top Layer w0.254: SDRV.7 9.738,66.939 9.738,66.228 9.683,66.173 9.683,64.327 10.989,63.021 12.295,63.021 13,62.317 13,61.546 12.5,61.046 v1(12.5,60) ; P1.15 26.476,10.677 35.798,20 43.912,20 44.061,20.149 44.061,20.586 44.209,20.734 44.221,20.734 44.544,21.057 ESP.23
  Bottom Layer w0.254: v1(12.5,60) 12.775,60 13.333,59.442 13.558,59.442 17.965,55.035 17.965,15.706 P1.15
IO17: ADRV.9 ESP.28 P2.2 | length 52.7
  Top Layer w0.254: ESP.28 49.144,26.417 49.669,25.892 49.691,25.892 50.027,25.555 50.027,24.857 52.404,22.48 52.404,20.884 53.406,19.882 53.406,16.943 54.596,15.753 54.596,12.915 P2.2 73.965,11.517 80.868,18.42 82.044,18.42 82.464,18 84.939,18 85.99,16.948 85.99,16.582 86.224,16.349 86.298,16.349 86.4,16.247 ADRV.9
IO18: C21.1 ESP.30 P2.4 R15.1 | length 62.7
  Top Layer w0.254: ESP.30 49.144,28.957 49.669,28.432 49.691,28.432 50.835,27.287 50.835,25.191 53.212,22.815 53.212,21.219 54.214,20.217 54.214,18.503 55.994,16.723 P2.4 ; v1(84.169,44.172) R15.1
  Bottom Layer w0.254: P2.4 62.534,16.597 84.169,38.232 v1(84.169,44.172) 82.269,44.172 C21.1
IO19: C18.1 ESP.31 P2.5 R14.1 | length 72.5
  Top Layer w0.254: ESP.31 49.144,30.227 49.669,29.702 49.691,29.702 51.239,28.153 51.239,25.359 53.616,22.982 53.616,21.515 P2.5 ; v1(82,59.5) 84.497,61.997 R14.1
  Bottom Layer w0.254: P2.5 68.436,31.58 68.588,31.58 68.716,31.707 69.076,31.707 69.644,32.275 69.675,32.275 80.5,43.1 80.5,58 v1(82,59.5) 82.194,59.694 82.678,59.694 83.26,60.277 83.377,60.277 C18.1
IO21: C15.1 ESP.33 P2.6 R13.1 | length 84.8
  Top Layer w0.254: ESP.33 51.233,32.767 51.643,32.357 51.643,26.357 55.994,22.006 P2.6 ; v1(83.994,73.997) 83.994,75.822 R13.1
  Bottom Layer w0.254: P2.6 66.3,31.984 68.421,31.984 69.904,33.467 69.904,34.729 80.096,44.921 80.096,59.917 83.994,63.814 v1(83.994,73.997) 82.194,73.997 C15.1
IO22: ESP.36 P2.9 | length 10.9
  Top Layer w0.254: ESP.36 49.994,36.577 52.855,33.716 52.855,32.436 P2.9
IO23: B2.5 B3.2 B4.2 ESP.37 P2.10 | length 65.5
  Top Layer w0.254: ESP.37 49.984,37.847 P2.10 ; v1(68,33) 69.128,31.872 69.128,29.527 68.851,29.25 B4.2 ; B3.2 68.283,47.273 68.66,47.273 68.946,47.56 68.946,48.171 69.5,48.725 v1(69.5,49) ; B2.5 70.757,64.974 71.104,64.974 72.042,64.037 72.042,63.211 73,62.252 v1(73,61)
  Bottom Layer w0.254: P2.10 57.156,33 v1(68,33) 68,35.063 70.411,37.474 70.411,42.912 69.5,43.823 v1(69.5,49) 73,52.5 v1(73,61)
IO25: ESP.10 P1.10 Rs2.1 S1.5 S1.6 | length 66.9
  Top Layer w0.254: P1.10 24.962,23.377 28.949,27.364 31.021,27.364 ESP.10 ; S1.6 S1.5 34.994,63.997 Rs2.1
  Bottom Layer w0.254: P1.10 28.433,28.817 28.433,51.466 33.615,56.647 34.372,56.647 35.16,57.434 35.16,60.94 34.245,61.855 34.245,62.746 S1.5
IO25_S: C31.1 Rs2.2 S2.5 S2.6 SRVB.1 SRVB.2 | length 47.6
  Top Layer w0.254: Rs2.2 51.154,63.997 S2.5 S2.6
  Bottom Layer w0.254: S2.6 55.476,65.697 70.509,80.73 74,80.73 74.003,80.727 74.994,80.727 74.994,83.267 76.339,83.267 76.969,83.897 C31.1 ; SRVB.2 SRVB.1
IO26: ESP.11 P1.11 Rs1.1 S1.1 S1.2 | length 68.1
  Top Layer w0.254: P1.11 28.574,26.417 ESP.11 ; S1.1 S1.2 38.799,55.377 42.169,58.747 Rs1.1
  Bottom Layer w0.254: P1.11 25.285,18.546 27.717,18.546 30.713,21.542 30.713,46.41 33.994,49.691 S1.1 S1.2
IO27: ESP.12 P1.12 SDRV.9 | length 66.9
  Top Layer w0.254: SDRV.9 10.744,66.091 10.491,65.838 10.491,64.662 11.323,63.829 12.727,63.829 v1(16.556,60) ; P1.12 25.727,21.031 25.727,22.671 28.203,25.147 ESP.12
  Bottom Layer w0.254: v1(16.556,60) 19.627,56.929 19.627,21.664 P1.12
IO32: ESP.8 P1.8 R24.1 | length 20.8
  Top Layer w0.254: R24.1 18.994,32.457 P1.8 24.764,30.227 ESP.8
IO33: ESP.9 P1.9 R25.1 | length 14.2
  Top Layer w0.254: R25.1 21.574,24.497 P1.9 25.681,25.917 28.398,28.634 31.021,28.634 ESP.9
IO34: ESP.6 JSW.2 P1.6 POW.1 POW.2 R22.2 | length 52.1
  Top Layer w0.254: P1.6 23.221,33.31 30.501,33.31 31.044,32.767 ESP.6 31.667,32.444 32.056,32.444 32.216,32.284 32.233,32.284 32.431,32.087 32.431,32.069 39.525,24.975 44.025,24.975 47.811,21.189 47.811,20.189 49.244,18.756 POW.1 49.244,10.622 R22.2@51.869,7.997 ; JSW.2 49,4.779 POW.2 49.244,5.147 51.396,7.299 51.396,7.524 R22.2@51.869,7.997 ; R22.2 R22.2@51.869,7.997
IO35: ESP.7 P1.7 R19.2 R20.1 R21.1 | length 46.6
  Top Layer w0.254: R19.2 24.176,62.997 R20.1 R21.1 24.181,59.753 23.883,59.455 23.633,59.455 21.873,57.694 21.194,57.694 v1(21,57.5) ; P1.7 23.358,30.997 23.858,31.497 ESP.7
  Bottom Layer w0.254: v1(21,57.5) 21,32.991 P1.7
NetACT_1: ACT.1 ADRV.3 | length 14.6
  Top Layer w0.3: ADRV.3 98.744,15.747 ACT.1
NetACT_2: ACT.2 ADRV.2 | length 13.8
  Top Layer w0.3: ADRV.2 100.664,15.247 ACT.2
NetADRV_11: ADRV.11 MODE2.2 R18.1 | length 11.3
  Top Layer w0.254: v1(81,16.5) 81.027,16.527 82.702,16.527 R18.1 83.003,16.822 84.974,16.822 85.182,16.614 85.182,16.248 85.889,15.541 85.96,15.541 86.248,15.253 ADRV.11@86.394,15.253
  Bottom Layer w0.254: v1(81,16.5) 81,16.522 84.454,19.975 MODE2.2
NetB1_2: B1.2 C5.1 L1.1 | length 8.3
  Top Layer w0.254: B1.2 9.017,52.474 9.364,52.474 9.862,51.977 9.862,50.8 10.394,50.268 L1.1 11.468,47.997 11.745,47.72 12.371,47.72 C5.1
NetB1_4: B1.4 C5.2 | length 4.6
  Top Layer w0.254: B1.4 10.437,51.997 10.414,51.974 10.414,50.819 11.713,49.52 12.371,49.52 C5.2
NetB1_6: B1.6 R5.2 R6.1 | length 3.9
  Top Layer w0.254: B1.6 12.819,52.997 R6.1 13,52.829 R5.2
NetB2_2: B2.2 C7.1 L2.1 | length 8.1
  Top Layer w0.254: C7.1 69.223,62.623 69.223,63.369 69.866,64.012 69.866,64.733 69.624,64.974 ; L2.1 69,67.377 69.866,66.512 69.866,65.262 69.624,65.02
NetB2_4: B2.4 C7.2 | length 2.6
  Top Layer w0.254: C7.2 70.734,62.334 B2.4
NetB2_6: B2.6 R7a.1 R8.1 | length 4.9
  Top Layer w0.254: B2.6 72.419,65.497 72.744,65.822 R8.1 72.994,66.922 72.169,67.747 R7a.1
NetB3_5: B3.5 C9.1 L3.1 | length 20
  Top Layer w0.254: B3.5 69.74,45.456 70.777,44.419 70.777,43.623 C9.1
  Top Layer w0.4: B3.5 76.29,46.25 79.589,49.549 79.589,50.451 78,52.04 L3.1
NetB3_6: B3.6 C9.2 | length 4.4
  Top Layer w0.254: C9.2 69.6,44.845 69.128,45.317 69.128,46.515 69.34,46.727 69.717,46.727 B3.6
NetB3_8: B3.8 R9.2 R10.1 | length 6.5
  Top Layer w0.254: B3.8 71.825,47.75 73.825,49.75 R9.2 R10.1
NetB4_5: B4.5 C11.1 L4.1 | length 18.3
  Top Layer w0.254: B4.5 69.74,27.206 70.277,26.669 70.277,25.623 C11.1
  Top Layer w0.4: B4.5 74.687,28.25 78.516,32.079 78.516,32.921 77,34.437 L4.1
NetB4_6: B4.6 C11.2 | length 4.5
  Top Layer w0.254: C11.2 69.1,26.163 69.276,26.339 69.276,27.181 69.055,27.402 69.055,28.545 69.26,28.75 B4.6
NetB4_8: B4.8 R11.2 R12.1 | length 6.7
  Top Layer w0.254: B4.8@69.825,29.75 69.848,29.727 70.336,29.727 70.579,29.484 71.421,29.484 72.016,30.079 72.016,31.441 72.825,32.25 R11.2 R12.1
NetC32_1: C32.1 LEDA.2 Rs1.2 S2.1 S2.2 | length 38.4
  Top Layer w0.254: v1(43.819,60.819) Rs1.2 43.819,58.747 47.029,55.537 S2.2 S2.1
  Bottom Layer w0.254: v1(43.819,60.819) 43.946,60.946 43.946,80.87 LEDA.2 47.894,80.997 C32.1
NetD1_1: D1.1 F1.1 MOTOR1.2 | length 15.2
  Top Layer w0.254: F1.1 90.639,78.366 D1.1 ; 99.914,77.997 MOTOR1.2
  Top Layer w0.4: F1.1 99.914,77.997
NetD2_1: D2.1 F2.1 MOTOR2.2 | length 16.1
  Top Layer w0.254: F2.1 90.639,65.366 D2.1
  Top Layer w0.4: F2.1 97.914,64.997 MOTOR2.2
NetD3_1: D3.1 F3.1 MOTOR3.2 | length 15.7
  Top Layer w0.4: D3.1 90.639,48.366 F3.1 98.914,47.997 MOTOR3.2
NetD4_1: D4.1 F4.1 MOTOR4.2 | length 15.7
  Top Layer w0.4: D4.1 90.639,33.366 F4.1 98.914,32.997 MOTOR4.2
NetESP_27: ESP.27 R2.2 | length 7.6
  Top Layer w0.254: ESP.27 49.144,25.147 49.669,24.622 49.691,24.622 52,22.313 R2.2
NetF1_2: F1.2 Q1.2 | length 2.9
  Top Layer w0.254: Q1.2 Q1.2@86.144,79.997 ; 87.291,78.85 87.291,78.423 F1.2
  Top Layer w0.4: Q1.2@86.144,79.997 87.291,78.85
NetF2_2: F2.2 Q2.2 | length 2.4
  Top Layer w0.254: Q2.2 Q2.2@86.267,65.624 ; F2.2@87.291,65.624 87.717,65.199 F2.2
  Top Layer w0.4: Q2.2@86.267,65.624 F2.2@87.291,65.624
NetF3_2: F3.2 Q3.2 | length 2.9
  Top Layer w0.254: Q3.2 86.144,49.997 87.291,48.85 87.291,48.423 F3.2
NetF4_2: F4.2 Q4.2 | length 3.5
  Top Layer w0.254: Q4.2 86.494,34.497 87.717,33.274 F4.2
NetIND1_2: IND1.2 R24.2 | length 6.5
  Top Layer w0.254: IND1.2 15.744,37.122 16.994,38.372 R24.2
NetIND2_2: IND2.2 R25.2 | length 6.4
  Top Layer w0.254: IND2.2 15.994,23.372 16.994,24.372 R25.2
NetLED1_1: LED1.1 R3.2 | length 3.5
  Top Layer w0.254: LED1.1 27.621,45.697 27.994,45.324 R3.2
NetLED2_1: LED2.1 R4.2 | length 6.5
  Top Layer w0.254: LED2.1 38.621,8.297 38.994,8.67 R4.2
NetMODE1_2: MODE1.2 R17.1 SDRV.11 | length 12.3
  Top Layer w0.254: MODE1.2 6.994,65.431 8.594,63.831 8.594,63.132 9.189,62.537 9.888,62.537 10.175,62.25 R17.1 ; SDRV.11 11.749,66.939 11.749,66.438 11.794,66.393 11.794,65.367 v1(11.911,65.25)
  Bottom Layer w0.254: MODE1.2 11.158,65.727 11.636,65.25 v1(11.911,65.25)
NetQ1_1: Q1.1 R13.2 | length 2.5
  Top Layer w0.254: R13.2 85.894,76.072 Q1.1
NetQ2_1: Q2.1 R14.2 | length 2.9
  Top Layer w0.254: Q2.1 85.894,63.172 86.819,62.247 R14.2
NetQ3_1: Q3.1 R15.2 | length 2.5
  Top Layer w0.254: R15.2 85.894,46.072 Q3.1
NetQ4_1: Q4.1 R16.2 | length 4.3
  Top Layer w0.254: Q4.1 85.244,32.997 87.521,30.72 87.521,30.295 R16.2
NetR7_2: R7.2 R7a.2 | length 2
  Top Layer w0.254: R7a.2 73.819,69.994 R7.2
NetSDRV_2: SDRV.2 STPA.2 | length 23
  Top Layer w0.3: SDRV.2 11.749,69.056 11.749,70.249 20,78.5 26.58,78.5 STPA.2
NetSDRV_3: SDRV.3 STPA.1 | length 18.7
  Top Layer w0.254: SDRV.3 SDRV.3@11.249,69.056
  Top Layer w0.3: SDRV.3@11.249,69.056 11.249,70.749 21.5,81 STPA.1
NetSDRV_4: SDRV.4 STPB.2 | length 13.3
  Top Layer w0.3: SDRV.4 10.744,77.744 STPB.2
NetSDRV_5: SDRV.5 STPB.1 | length 12.5
  Top Layer w0.3: STPB.1 10.244,79.676 SDRV.5
RX: ESP.34 P2.7 | length 14
  Top Layer w0.254: ESP.34 50.963,34.037 52.047,32.953 52.047,28.953 55.807,25.193 55.807,24.404 P2.7
TX: ESP.35 P2.8 | length 12.6
  Top Layer w0.254: ESP.35 50.693,35.307 52.451,33.549 52.451,30.549 55.994,27.006 P2.8
VN: ESP.5 P1.5 | length 9.2
  Top Layer w0.254: P1.5 25.034,34.037 ESP.5
VP: ESP.4 P1.4 | length 9.9
  Top Layer w0.254: P1.4 26.491,35.12 28.844,35.12 29.031,35.307 ESP.4
pads on no net: ADRV.4 ADRV.5 ADRV.7 ADRV.8 B3.1 B3.7 B4.1 B4.7 D1.3 D2.3 D3.3 D4.3 ESP.17 ESP.18 ESP.19 ESP.20 ESP.21 ESP.22 ESP.32 P2.11 P2.12 P2.13 P2.14 P2.16

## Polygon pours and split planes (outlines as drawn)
14.4V on Top Layer "14.4V_L01_P024" (solid, pour order 24): 63.74,28.5 64,28.5 64.5,28 68.76,28 67.76,29.5 64,29.5 63.74,29.24
10.4VB on Top Layer "10.4VB_L01_P022" (solid, pour order 22): 68.5,40.5 67.5,39.5 67.5,38 68,37.5 69,37.5 70,36.5 70,34 70.5,33.5 70.5,31.5 71.5,31.5 72,32 72,35 75,38 85,38 89,34 100,34 101,33 103.5,33 104,33.5 104,36.5 102,38.5 89.5,38.5 89.5,49 100.5,49 101,48.5 103.5,48.5 104,49 104,51 103,52 94,52 94,53 93,54 89,54 88.5,53.5 88.5,42 87,40.5
14.4V on Top Layer "14.4V_L01_P015" (solid, pour order 15): 23,70 18,65 18,59 11.5,59 8,55.5 8,53.281 8.565,52.716 8.571,52.722 9.411,52.722 11.5,54.811 11.5,56 12.5,57 19,57 20,58 20,64.5 21.5,64.5 23,66
6V on Top Layer "6V_L01_P016" (solid, pour order 16): 12.433,69.448 12.245,69.448 12.034,69.237 12.034,68.838 12.891,67.981 19.646,67.981 26.114,74.449 63.051,74.449 67,70.5 70.5,70.5 72,69 72.5,69 73,69.5 73,71 73.5,71 74,71.5 74,74 75.5,75.5 75.5,77 70,82.5 51.5,82.5 47,78 47,76.5 46.5,76 24,76 17.5,69.5
14.4V on Top Layer "14.4V_L01_P005" (solid, pour order 5): 23,66 29,66 33,70 60.5,70 63.74,66.76 63.74,28.5 67,28.5 67,69 63,73 26,73 23,70
10.4VA on Top Layer "10.4VA_L01_P020" (solid, pour order 20): 69,58 68.469,57.469 68.469,55.531 69.5,54.5 70,54.5 70,50.5 71.5,49 72.5,49 73,49.5 73,53.5 75,55.5 88,55.5 89.5,57 89.5,67.5 90,68 92.5,65.5 100,65.5 100,65 101,64 104,64 104.5,64.5 104.5,67.5 104,68 100.5,68 100,67.5 96,67.5 89.5,74 89.5,79.618 103.118,79.618 103.5,80 103.5,82 103,82.5 92,82.5 90.5,84 89.5,84 88.85,83.35 88.85,82.35 88.316,81.816 88.316,58.316 88,58
3.3V on Top Layer "3.3V_L01_P009" (solid, pour order 9): 5,54 6,53 6,51 7,50 8,50 9,49 9,47 10,46 21,46 22,45 24,45 27,42 30,42 31,41 31,39 32,38 32,37 27.286,37 24,40.5 24,41.5 22,43 20,44 5,44 4.232,44.768 4.232,47.768 2,50 2,53 3,54 4,54 3,54 4,54
14.4V on Top Layer "14.4V_L01_P017" (solid, pour order 17): 66.791,44.427 68.667,46.755 66.791,49.818
14.4V on Top Layer "14.4V_L01_P008" (solid, pour order 8): 67,62.5 70,65.5 70,66 67,69
GND on Bottom Layer "GND_L02_P003" (solid, pour order 3): 0.044,5.033 0.044,85.033 cw(c5.044,85.033) 5.044,90.033 105.044,90.033 cw(c105.044,85.033) 110.044,85.033 110.044,5.033 cw(c105.044,5.033) 105.044,0.033 5.044,0.033 cw(c5.044,5.033)

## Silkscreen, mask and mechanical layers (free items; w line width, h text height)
Top Overlay:
  drawing of 277 lines, arcs and shapes, not listed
